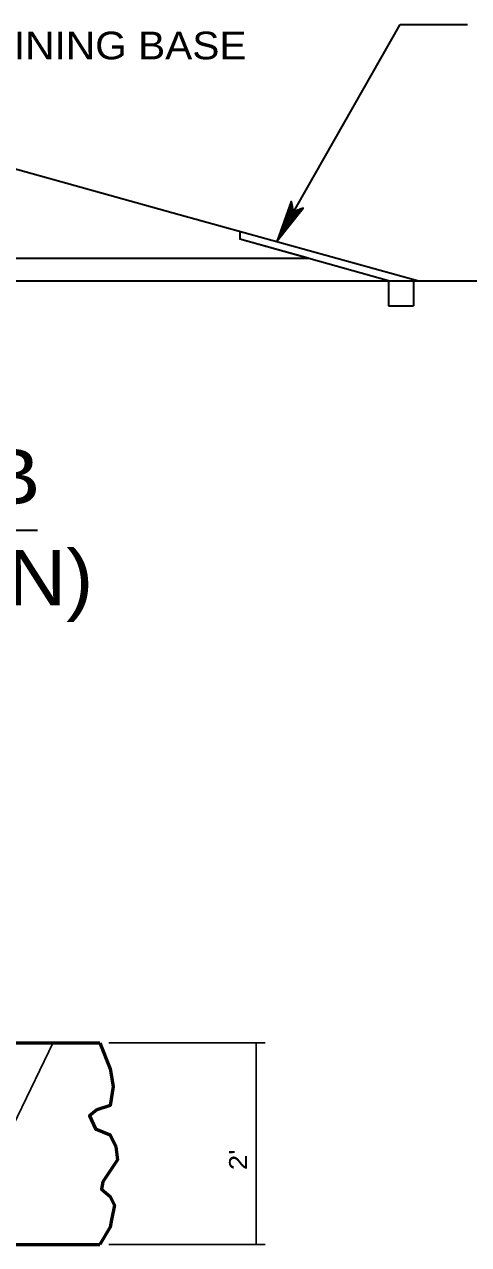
# Model space of a CAD drawing. Extents: x -48732 to -48696.6, y -117659.8 to -117637.8.
# Drawn here: x -48722.25 to -48720.32, y -117654.16 to -117648.86 of the extents above; entities that cross this region are included whole.
import ezdxf

# ---------------------------------------------------------------- set-up
doc = ezdxf.new("R2010")
doc.units = 0
doc.header["$LTSCALE"] = 0.048
for name, color, linetype, lineweight in [('11', 7, 'Continuous', 25), ('24', 7, 'Continuous', 40), ('3', 7, 'Continuous', 35)]:
    doc.layers.add(name, color=color, linetype=linetype, lineweight=lineweight)

msp = doc.modelspace()

# ---------------------------------------------------------------- linework, layer by layer
at = {"layer": '11'}
for p, q in [((-48721.88708, -117653.27983), (-48721.20883, -117653.27983)), ((-48721.248, -117654.15533), (-48721.248, -117653.27983)), ((-48721.88708, -117654.15533), (-48721.20883, -117654.15533))]:
    msp.add_line(p, q, dxfattribs=at)
msp.add_lwpolyline([(-48722.12933, -117653.2785), (-48722.4405, -117653.9205), (-48722.57717, -117653.9205)], dxfattribs=at)
at = {"layer": '24', "lineweight": 53}
for p, q in [((-48724.64383, -117653.27983), (-48721.92617, -117653.27983)), ((-48727.68467, -117654.15533), (-48721.92617, -117654.15533))]:
    msp.add_line(p, q, dxfattribs=at)
msp.add_lwpolyline([(-48721.92617, -117653.27983), (-48721.88158, -117653.393), (-48721.86883, -117653.46917), (-48721.88158, -117653.55183), (-48721.93867, -117653.57092), (-48721.9705, -117653.59633), (-48721.94508, -117653.6535), (-48721.88158, -117653.679), (-48721.85617, -117653.72983), (-48721.84983, -117653.787), (-48721.91333, -117653.88233), (-48721.91967, -117653.91417), (-48721.88158, -117653.94592), (-48721.8625, -117653.984), (-48721.87517, -117654.04767), (-48721.88158, -117654.07933), (-48721.92617, -117654.15533)], dxfattribs=at)
at = {"layer": '3'}
for p, q in [((-48721.15683, -117649.799), (-48720.6225, -117648.85942)), ((-48720.6225, -117648.85942), (-48720.3295, -117648.85942)), ((-48721.318, -117649.76117), (-48721.318, -117649.79117)), ((-48720.67225, -117649.973), (-48721.318, -117649.79117)), ((-48721.0215, -117649.87367), (-48721.31792, -117649.79092)), ((-48724.72167, -117649.87367), (-48721.0215, -117649.87367)), ((-48724.79483, -117649.973), (-48719.98, -117649.973)), ((-48720.67225, -117649.973), (-48720.67225, -117650.081)), ((-48720.56425, -117649.973), (-48720.56425, -117650.081)), ((-48720.67225, -117650.081), (-48720.56425, -117650.081)), ((-48723.95158, -117651.05517), (-48722.19658, -117651.05517))]:
    msp.add_line(p, q, dxfattribs=at)
for points in [[(-48720.54708, -117649.973), (-48721.58208, -117649.68525), (-48722.94875, -117649.30533)], [(-48721.09583, -117649.6275), (-48721.15683, -117649.799), (-48721.04392, -117649.65633), (-48721.04858, -117649.65775), (-48721.14808, -117649.78292), (-48721.0945, -117649.63233), (-48721.09375, -117649.63833), (-48721.13908, -117649.76692), (-48721.05417, -117649.66033), (-48721.05967, -117649.66292), (-48721.13017, -117649.75083), (-48721.09317, -117649.64442), (-48721.09133, -117649.65017), (-48721.12133, -117649.73475), (-48721.06542, -117649.66458), (-48721.071, -117649.66725), (-48721.11308, -117649.71992), (-48721.09075, -117649.65625), (-48721.08908, -117649.66192), (-48721.10408, -117649.70392), (-48721.07667, -117649.66892), (-48721.08217, -117649.6715), (-48721.09517, -117649.68775), (-48721.0885, -117649.668), (-48721.09583, -117649.6275), (-48721.08708, -117649.67283), (-48721.04392, -117649.65633)]]:
    msp.add_lwpolyline(points, dxfattribs=at)

# ---------------------------------------------------------------- texts
at = {"layer": '11', "width": 1.15}
msp.add_text("   2'", height=0.07812, rotation=90, dxfattribs=at).set_placement((-48721.287, -117653.93233))
at = {"layer": '3'}
for s, height, width, p in [('FREE DRAINING BASE', 0.12, 1.1, (-48723.19208, -117649.011)), ('DETAIL B', 0.24, 1.15, (-48723.825, -117650.942)), ('(ELEVATION)', 0.24, 1.1, (-48724.17125, -117651.38025))]:
    msp.add_text(s, height=height, dxfattribs=dict(at, width=width)).set_placement(p)

doc.saveas('drawing.dxf')
